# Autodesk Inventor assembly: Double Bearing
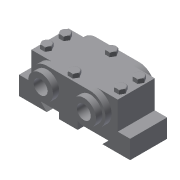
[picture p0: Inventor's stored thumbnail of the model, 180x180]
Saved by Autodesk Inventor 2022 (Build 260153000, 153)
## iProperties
Created: 2002-02
Part Number: Double Bearing
Document SubType Name: Assembly
Designer: ***
Control State: 0
Master: False
Checked Out: False
Shininess: 64.0
Length Units: 11269
Angle Units: 11279
Time Units: 11290
Mass Units: 11283
Length Display Precision: 3
Angle Display Precision: 2
Density: 0.0
Volumn: 0.0
Area: 0.0
PropertySet Name: Model Information
Author: ***
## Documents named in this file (5)
- D:\PROJECTS_2021\Resources\Part Files\c12_Inv_2022_prt\fig-12-10 and 12-18\Double Bearing.iam
- D:\PROJECTS_2021\Resources\Part Files\c12_Inv_2022_prt\fig-12-10 and 12-18\Base.ipt
- D:\PROJECTS_2021\Resources\Part Files\c12_Inv_2022_prt\fig-12-10 and 12-18\Cap.ipt
- D:\PROJECTS_2021\Resources\Part Files\c12_Inv_2022_prt\fig-12-10 and 12-18\Bushing.ipt
- D:\PROJECTS_2021\Resources\Part Files\c12_Inv_2022_prt\fig-12-10 and 12-18\Bolt.ipt
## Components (10 placed, 4 different names)
1. Base:1 — Insert:1, Insert:2
2. Cap:1 — Insert:1, Insert:2, Insert:3, Insert:4, Insert:5, Insert:6
3. Bushing:1 — Insert:3
4. Bushing:2 — Insert:4
5. Bolt:1 — Insert:5
6. Bolt:6
7. Bolt:7
8. Bolt:8
9. Bolt:5 — Insert:6
10. Bolt:9
## Component patterns: Component Pattern 1 (4 elements), Component Pattern 2 (2 elements)
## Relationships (6: Insert 6)
- Insert:1: Base:1 ↔ Cap:1
- Insert:2: Base:1 ↔ Cap:1
- Insert:3: Cap:1 ↔ Bushing:1
- Insert:4: Cap:1 ↔ Bushing:2
- Insert:5: Cap:1 ↔ Bolt:1
- Insert:6: Cap:1 ↔ Bolt:5
